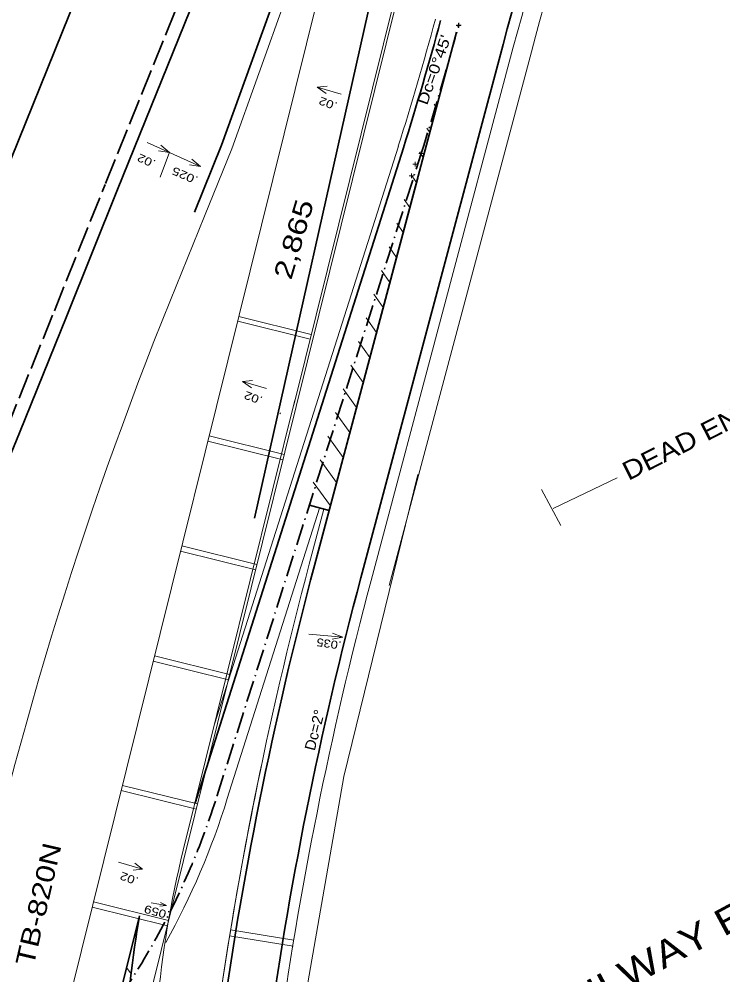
# Model space of a CAD drawing. Extents: x 2354993 to 2372084, y 6966390 to 6990057.
# Drawn here: x 2364746 to 2365274, y 6979180 to 6979897 of the extents above; entities that cross this region are included whole.
import ezdxf

# ---------------------------------------------------------------- set-up
doc = ezdxf.new("R2010")
doc.units = 0
doc.header["$LTSCALE"] = 3.2
doc.linetypes.add('DOT_DASHED', pattern=[7.7, 5, -1.2, 0.3, -1.2])
doc.linetypes.add('LONG_DASHED', pattern=[7.5, 6, -1.5])
for name, color, linetype, lineweight in [('1', 7, 'Continuous', 13), ('13', 7, 'Continuous', 13), ('17', 7, 'Continuous', 13), ('19', 7, 'Continuous', 13), ('2', 7, 'Continuous', 35), ('23', 7, 'Continuous', 13), ('5', 7, 'Continuous', 35), ('6', 7, 'Continuous', 35), ('61', 7, 'Continuous', 13), ('7', 7, 'Continuous', 13), ('9', 7, 'Continuous', 13)]:
    doc.layers.add(name, color=color, linetype=linetype, lineweight=lineweight)

msp = doc.modelspace()

# ---------------------------------------------------------------- linework, layer by layer
at = {"layer": '1'}
for p, q in [((2365077.464, 6979892.584), (2365073.964, 6979892.584)), ((2365077.556, 6979892.776), (2365074.056, 6979892.776)), ((2365077.556, 6979892.776), (2365074.056, 6979892.776)), ((2365077.556, 6979892.776), (2365074.056, 6979892.776)), ((2365075.714, 6979894.334), (2365075.714, 6979890.834)), ((2365075.806, 6979894.526), (2365075.806, 6979891.026)), ((2365075.806, 6979894.526), (2365075.806, 6979891.026)), ((2365075.806, 6979894.526), (2365075.806, 6979891.026)), ((2365049.425, 6979796.588), (2365045.925, 6979796.588)), ((2365047.675, 6979798.338), (2365047.675, 6979794.838)), ((2365044.976, 6979788.49), (2365041.476, 6979788.49)), ((2365044.976, 6979788.49), (2365041.476, 6979788.49)), ((2365043.226, 6979790.24), (2365043.226, 6979786.74)), ((2365043.226, 6979790.24), (2365043.226, 6979786.74)), ((2365040.342, 6979781.355), (2365040.342, 6979777.855)), ((2365042.092, 6979779.605), (2365038.592, 6979779.605))]:
    msp.add_line(p, q, dxfattribs=at)
at = {"layer": '13', "lineweight": 35}
msp.add_line((2364922.585, 6979522.917), (2365036.612, 6980031.444), dxfattribs=at)
at = {"layer": '17'}
for p, q in [((2364969.717, 6979846.32), (2364977.167, 6979846.989)), ((2364913.656, 6979625.58), (2364921.106, 6979626.249)), ((2364838.514, 6979259.789), (2364820.521, 6979265.065)), ((2364838.514, 6979259.789), (2364832.75, 6979264.248)), ((2364838.514, 6979259.789), (2364831.573, 6979258.986)), ((2364856.678, 6979232.519), (2364851.515, 6979231.94))]:
    msp.add_line(p, q, dxfattribs=at)
for points in [[(2364987.709, 6979841.045), (2364969.716, 6979846.321), (2364976.272, 6979841.429)], [(2364931.647, 6979620.306), (2364913.654, 6979625.582), (2364920.211, 6979620.689)], [(2364845.118, 6979234.449), (2364856.678, 6979232.519), (2364851.986, 6979234.747)]]:
    msp.add_lwpolyline(points, dxfattribs=at)
at = {"layer": '19'}
for p, q in [((2364858.74, 6979797.296), (2364852.347, 6979802.598)), ((2364858.74, 6979797.296), (2364850.508, 6979798.436)), ((2364851.801, 6979778.744), (2364858.845, 6979797.443)), ((2364882.037, 6979786.826), (2364873.805, 6979787.966)), ((2364988.942, 6979433.834), (2364980.787, 6979432.231))]:
    msp.add_line(p, q, dxfattribs=at)
for points in [[(2364841.954, 6979804.669), (2364882.037, 6979786.826), (2364875.644, 6979792.128)], [(2364963.249, 6979435.987), (2364988.942, 6979433.834), (2364981.172, 6979436.768)]]:
    msp.add_lwpolyline(points, dxfattribs=at)
at = {"layer": '2'}
for p, q in [((2364697.647, 6979688.336), (2364930.731, 6980264.109)), ((2365007.434, 6980233.06), (2364819.815, 6979769.595)), ((2364781.72, 6979674.823), (2364819.815, 6979769.595)), ((2364746.17, 6979587.006), (2364781.72, 6979674.823))]:
    msp.add_line(p, q, dxfattribs=at)
at = {"layer": '2', "linetype": 'LONG_DASHED'}
for p, q in [((2364998.165, 6980236.812), (2364810.546, 6979773.347)), ((2364772.442, 6979678.553), (2364810.537, 6979773.325)), ((2364736.901, 6979590.758), (2364772.451, 6979678.575))]:
    msp.add_line(p, q, dxfattribs=at)
at = {"layer": '2'}
msp.add_arc((2367364.087, 6978527.237), 2824.289, 157.96111, 179.32363, dxfattribs=at)
at = {"layer": '23'}
for p, q in [((2365023.63, 6979472.53), (2365130.321, 6979872.599)), ((2364989.616, 6979329.308), (2365045.088, 6979555.624)), ((2364955.036, 6979131.858), (2364989.616, 6979329.308))]:
    msp.add_line(p, q, dxfattribs=at)
msp.add_arc((2367865.518, 6979143.17), 2830.789, 157.35649, 165.06774, dxfattribs=at)
at = {"layer": '5', "lineweight": 13}
for p, q in [((2364760.631, 6978828.473), (2365077.413, 6980104.485)), ((2364952, 6979607.617), (2365075.472, 6980104.967)), ((2364704.339, 6978842.448), (2365012.522, 6980083.82)), ((2364905.475, 6979799.995), (2365008.116, 6980085.603)), ((2365010.102, 6979476.137), (2365116.794, 6979876.206)), ((2365057.509, 6979833.455), (2365059.219, 6979831.07)), ((2365051.935, 6979815.488), (2365054.216, 6979812.308)), ((2364905.475, 6979799.995), (2364885.023, 6979749.457)), ((2365046.328, 6979797.568), (2365049.212, 6979793.546)), ((2365040.687, 6979779.694), (2365044.209, 6979774.784)), ((2365035.013, 6979761.868), (2365039.205, 6979756.022)), ((2364859.546, 6979686.522), (2364885.023, 6979749.457)), ((2365029.293, 6979744.104), (2365034.202, 6979737.26)), ((2365023.561, 6979726.358), (2365029.198, 6979718.498)), ((2365017.829, 6979708.612), (2365024.195, 6979699.736)), ((2365012.097, 6979690.867), (2365019.191, 6979680.974)), ((2365006.365, 6979673.121), (2365014.188, 6979662.212)), ((2365000.633, 6979655.375), (2365009.184, 6979643.45)), ((2364994.9, 6979637.629), (2365004.181, 6979624.688)), ((2364989.168, 6979619.883), (2364999.177, 6979605.926)), ((2364869.155, 6979273.916), (2364952.974, 6979611.544)), ((2364942.18, 6979601.264), (2364941.597, 6979602.077)), ((2364983.436, 6979602.137), (2364994.174, 6979587.164)), ((2364977.704, 6979584.391), (2364989.17, 6979568.403)), ((2364971.972, 6979566.645), (2364984.167, 6979549.641)), ((2364966.622, 6979550.083), (2364979.497, 6979532.129)), ((2365152.455, 6979517.382), (2365137.889, 6979544.461)), ((2364902.17, 6979312.668), (2364971.472, 6979530.58)), ((2364963.723, 6979488.506), (2364974.713, 6979529.715)), ((2364826.593, 6979185.972), (2364830.037, 6979181.168))]:
    msp.add_line(p, q, dxfattribs=at)
at = {"layer": '5'}
for p, q in [((2364897.947, 6979802.7), (2364999.406, 6980085.023)), ((2364967.588, 6979487.475), (2365074.28, 6979887.544)), ((2365002.373, 6979478.198), (2365109.064, 6979878.268)), ((2364897.947, 6979802.7), (2364877.608, 6979752.459)), ((2364967.588, 6979487.475), (2365045.124, 6979778.215)), ((2364978.578, 6979528.685), (2364963.733, 6979532.643)), ((2364775.353, 6978982.176), (2364836.312, 6979224.63))]:
    msp.add_line(p, q, dxfattribs=at)
at = {"layer": '5', "lineweight": 13}
msp.add_lwpolyline([(2364892.613, 6979368.406), (2365030.521, 6979802.044), (2365030.511, 6979802.011)], dxfattribs=at)
at = {"layer": '5'}
msp.add_lwpolyline([(2364881.181, 6979319.258), (2364881.205, 6979319.336), (2365034.333, 6979800.831), (2365034.325, 6979800.806)], dxfattribs=at)
for centre, radius, start, end in [((2367865.518, 6979143.17), 2852.789, 157.35649, 165.06774), ((2362862.313, 6980487.013), 2277.831, 342.46704, 344.96741), ((2367758.826, 6978743.101), 2888.789, 165.06774, 172.27016), ((2367758.826, 6978743.101), 2852.789, 165.06774, 172.27016), ((2364347.535, 6979485.558), 558.958, 341.57402, 342.6914), ((2365602.828, 6979091.775), 777.944, 170.16699, 184.0701)]:
    msp.add_arc(centre, radius, start, end, dxfattribs=at)
at = {"layer": '5', "lineweight": 13}
for centre, radius, start, end in [((2367865.518, 6979143.17), 2844.789, 157.35649, 165.06774), ((2362862.313, 6980487.013), 2273.831, 342.46704, 344.96741), ((2367632.916, 6978563.811), 2992, 157.9609, 178.42915), ((2367758.826, 6978743.101), 2892.789, 165.06774, 172.27016), ((2367758.826, 6978743.101), 2844.789, 165.06774, 172.27016), ((2367758.826, 6978743.101), 2892.789, 168.1183, 172.27016), ((2364347.535, 6979485.558), 580.958, 331.09011, 342.6914), ((2365602.828, 6979091.775), 755.944, 166.05766, 184.04951)]:
    msp.add_arc(centre, radius, start, end, dxfattribs=at)
at = {"layer": '6', "linetype": 'DOT_DASHED'}
msp.add_line((2364894.547, 6979315.093), (2365047.675, 6979796.588), dxfattribs=at)
for centre, radius, start, end in [((2362862.313, 6980487.013), 2291.831, 342.46704, 344.96741), ((2364347.535, 6979485.558), 572.958, 296.29328, 342.6914)]:
    msp.add_arc(centre, radius, start, end, dxfattribs=at)
at = {"layer": '61'}
for p, q in [((2364910.816, 6979674.145), (2364965.166, 6979660.652)), ((2364909.973, 6979670.748), (2364964.323, 6979657.255)), ((2364887.629, 6979580.746), (2364944.124, 6979566.72)), ((2364888.592, 6979584.628), (2364944.8, 6979570.674)), ((2364868.112, 6979502.132), (2364924.32, 6979488.178)), ((2364867.148, 6979498.25), (2364923.643, 6979484.225)), ((2364846.668, 6979415.754), (2364903.163, 6979401.729)), ((2364847.632, 6979419.636), (2364903.839, 6979405.682)), ((2364823.537, 6979322.582), (2364879.745, 6979308.628)), ((2364822.573, 6979318.7), (2364879.068, 6979304.675)), ((2364800.888, 6979231.352), (2364857.383, 6979217.326)), ((2364801.852, 6979235.234), (2364858.06, 6979221.28)), ((2364904.474, 6979214.146), (2364952.112, 6979206.401)), ((2364903.924, 6979209.67), (2364951.562, 6979201.925))]:
    msp.add_line(p, q, dxfattribs=at)
at = {"layer": '7'}
msp.add_line((2365194.839, 6979553.307), (2365146.764, 6979530.287), dxfattribs=at)
at = {"layer": '9'}
msp.add_arc((2360722.521, 6984327.136), 5729.573, 359.50797, 359.50797, dxfattribs=at)

# ---------------------------------------------------------------- texts
at = {"layer": '13'}
for s, height, rotation, width, p in [('2,865', 14, 73.545, 1.3, (2364950.088, 6979701.037)), ('TRINITY RAILWAY EXPRESS', 20, 28.245, 1.2, (2365021.709, 6979072.937)), ('TB-820N', 14, 76.983, 1.25, (2364756.765, 6979186.258))]:
    msp.add_text(s, height=height, rotation=rotation, dxfattribs=dict(at, width=width)).set_placement(p)
at = {"layer": '17'}
for s, height, rotation, width, p in [("Dc=0°45'", 8, 70.548, 1.25, (2365052.084, 6979832.294)), ('.02', 6, 159.81, 1.25, (2364985.344, 6979834.38)), ('.02', 6, 159.81, 1.25, (2364929.282, 6979613.641)), ('Dc=2°', 8, 75.543, 1.05, (2364967.737, 6979348.071)), ('.02', 6, 159.81, 1.25, (2364836.149, 6979253.124)), ('.059', 6, 164.81, 1.25, (2364859.614, 6979227.898))]:
    msp.add_text(s, height=height, rotation=rotation, dxfattribs=dict(at, width=width)).set_placement(p)
at = {"layer": '19'}
for s, rotation, width, p in [('.02', 156.266, 1.25, (2364849.102, 6979790.993)), ('.025', 156.502, 1.3, (2364880.917, 6979778.65)), ('.035', 171.703, 1.2, (2364988.165, 6979430.35))]:
    msp.add_text(s, height=6, rotation=rotation, dxfattribs=dict(at, width=width)).set_placement(p)
at = {"layer": '7', "width": 1.15}
msp.add_text('DEAD END', height=14, rotation=26.686, dxfattribs=at).set_placement((2365203.148, 6979550.89))

doc.saveas('drawing.dxf')
